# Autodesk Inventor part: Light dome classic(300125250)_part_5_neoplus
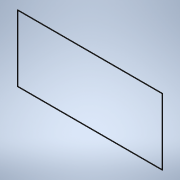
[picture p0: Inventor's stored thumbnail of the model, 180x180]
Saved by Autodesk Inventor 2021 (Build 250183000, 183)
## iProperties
Created: 2026-04
Part Number: Light dome classic(300125250)_part_5_neoplus
Material: Generic
Catalog Web Link: www.3dfindit.com
Description: Light dome classic_part_5_neoplus-
Vendor: KINGSPAN
Document SubType Name: Modeling
Designer: psAdmin
Manufacturer: KINGSPAN
Mass: 778.027 g
Surface Area: 2919.62 cm^2
Volume: 778.027 cm^3
Density: 1 g/cm^3
Appearance: PSOLRGB-128-128-128
Category: PARTsolutions
Company: KINGSPAN
Title: Light dome classic(300125250)_part_5_neoplus
Author: Cadenas PARTsolutions
PSOL_IDENT_0: {$CADENAS_DATA/23d-libs/kingspan_kla/light_dome_classic_neoplus/parts/part_5.prj},268 {VTYP=3D},{NB=
PSOL_IDENT_1: Light dome classic(300125250)_part_5_neoplus},{LINA=Light dome classic(300125250)_part_5_neoplus},{N
PSOL_IDENT_2: N=Light dome classic_part_5_neoplus},{DATE=20.03.2025 09:30:52},{GEOMDATE=21.11.2022 13:10:00},{VERS
PSOL_IDENT_3: ION=},{LINEID=10},{WBVAR=LODLEVEL,L,W},{WBNUMERIC=W}  {NB=Light dome classic(300125250)_part_5_neopl
PSOL_IDENT_4: us},{LINA=Light dome classic(300125250)_part_5_neoplus},{KT=DUMMY},{IDNR=},{PN=Light dome classic},{
PSOL_IDENT_5: LODLEVEL=300},{L=125},{W=250},{WX=125,250,300},{LX=1250},{XWX=2500}
NB: Light dome classic(300125250)_part_5_neoplus
NN: Light dome classic_part_5_neoplus
NBSYN: $PN.($LODLEVEL.$L.$W.)_part_5_neoplus
LINA: Light dome classic(300125250)_part_5_neoplus
CATALOG: Light + Air
PN: Light dome classic
LODLEVEL: 300
L: 125
W: 250
SUPPLIER: KINGSPAN
ARTICLENO: Light dome classic(300125250)_part_5_neoplus
BOMINFO: Light dome classic(300125250)_part_5_neoplus
CREATOR: CADENAS GmbH
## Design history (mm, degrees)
sketch "Sketch_1"
  geometry: L1 (-1145.21, 12.944)-(-1145.21, 25.446); L2 (-1145.21, 25.446)-(-1154.5, 25.446); L3 (-1154.5, 25.446)-(-1154.5, 12.944); L4 (-1154.5, 12.944)-(-1145.21, 12.944)
  constraints: 8 end point
extrude "Extrusion1" join sketch "Sketch_1" stored distance "d0" = 2500; taper "d1" = 0 deg
sketch "Sketch_2"
  geometry: L1 (529.5, 25.446)-(520.21, 25.446); L2 (520.21, 25.446)-(520.21, 12.944); L3 (520.21, 12.944)-(529.5, 12.944); L4 (529.5, 12.944)-(529.5, 25.446)
  constraints: 8 end point
extrude "Extrusion2" join sketch "Sketch_2" stored distance "d2" = 5000; taper "d3" = 0 deg
sketch "Sketch_3"
  geometry: L1 (1154.5, 12.944)-(1154.5, 25.446); L2 (1154.5, 25.446)-(1145.21, 25.446); L3 (1145.21, 25.446)-(1145.21, 12.944); L4 (1145.21, 12.944)-(1154.5, 12.944)
  constraints: 8 end point
extrude "Extrusion3" join sketch "Sketch_3" stored distance "d4" = 2500; taper "d5" = 0 deg
sketch "Sketch_4"
  geometry: L1 (-529.5, 25.446)-(-529.5, 12.944); L2 (-529.5, 12.944)-(-520.21, 12.944); L3 (-520.21, 12.944)-(-520.21, 25.446); L4 (-520.21, 25.446)-(-529.5, 25.446)
  constraints: 8 end point
extrude "Extrusion4" join sketch "Sketch_4" stored distance "d6" = 5000; taper "d7" = 0 deg
sketch "Sketch_5"
  geometry: L1 (-1154.5, 3.096)-(-1154.5, 25.446); L2 (-1154.5, 25.446)-(-3646.516, 25.446); L3 (-3646.516, 25.446)-(-3646.516, 3.096); L4 (-3646.516, 3.096)-(-1154.5, 3.096)
  constraints: 8 end point
extrude "Extrusion5" cut sketch "Sketch_5" stored distance "d8" = 5000; taper "d9" = 0 deg
sketch "Sketch_6"
  geometry: L1 (3021.516, 25.446)-(529.5, 25.446); L2 (529.5, 25.446)-(529.5, 3.096); L3 (529.5, 3.096)-(3021.516, 3.096); L4 (3021.516, 3.096)-(3021.516, 25.446)
  constraints: 8 end point
extrude "Extrusion6" cut sketch "Sketch_6" stored distance "d10" = 5000; taper "d11" = 0 deg
sketch "Sketch_7"
  geometry: L1 (3646.516, 25.446)-(1154.5, 25.446); L2 (1154.5, 25.446)-(1154.5, 3.096); L3 (1154.5, 3.096)-(3646.516, 3.096); L4 (3646.516, 3.096)-(3646.516, 25.446)
  constraints: 8 end point
extrude "Extrusion7" cut sketch "Sketch_7" stored distance "d12" = 5000; taper "d13" = 0 deg
sketch "Sketch_8"
  geometry: L1 (-3021.516, 25.446)-(-3021.516, 3.096); L2 (-3021.516, 3.096)-(-529.5, 3.096); L3 (-529.5, 3.096)-(-529.5, 25.446); L4 (-529.5, 25.446)-(-3021.516, 25.446)
  constraints: 8 end point
extrude "Extrusion8" cut sketch "Sketch_8" stored distance "d14" = 5000; taper "d15" = 0 deg
node "IP_5_XY"
node "IP_5_YZ"
node "IP_5_ZX"
node "IP_5_X"
node "IP_5_Y"
node "IP_5_Z"
node "IP_5_Center"
body "Solid1"
other parameters: "d16" = 0
